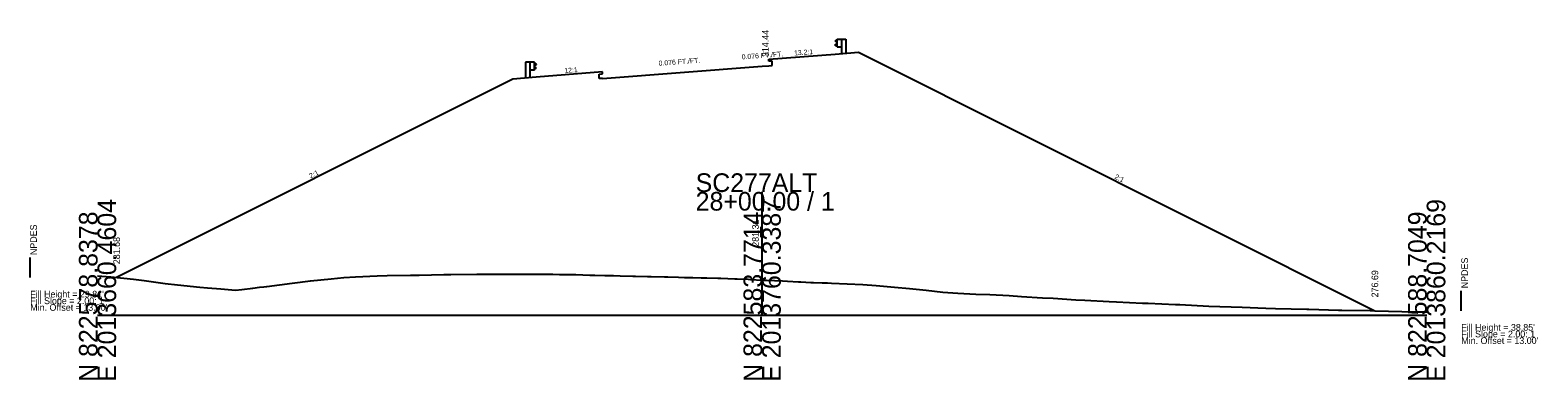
# Model space of a CAD drawing. Extents: x 205929 to 2357175, y -1785700 to 827636.
# Drawn here: x 2017410 to 2017636.9, y 826034.6 to 826087.1 of the extents above; entities that cross this region are included whole.
import ezdxf

# ---------------------------------------------------------------- set-up
doc = ezdxf.new("R2010")
doc.units = 0
for name, color, linetype in [('RD_GPK_XS_Cell', 7, 'Continuous'), ('RD_XS_Base', 7, 'Continuous'), ('RD_XS_EarthShd', 7, 'Continuous'), ('RD_XS_ExGround', 7, 'Continuous'), ('RD_XS_GR', 7, 'Continuous'), ('RD_XS_NPDES', 7, 'Continuous'), ('RD_XS_Pave', 7, 'Continuous'), ('RD_XS_TieSlope', 7, 'Continuous'), ('RD_XS_TX_Elev_EX', 7, 'Continuous'), ('RD_XS_TX_Elev_PR', 7, 'Continuous'), ('RD_XS_TX_ShdSlope', 7, 'Continuous'), ('RD_XS_TX_Slope', 7, 'Continuous'), ('RD_XS_TX_Warning', 7, 'Continuous')]:
    doc.layers.add(name, color=color, linetype=linetype)

msp = doc.modelspace()

# ---------------------------------------------------------------- linework, layer by layer
at = {"layer": 'RD_GPK_XS_Cell'}
for p, q in [((2017520.17, 826044.26), (2017520.17, 826062.8)), ((2017420.17, 826044.26), (2017520.17, 826044.26)), ((2017520.17, 826044.26), (2017620.17, 826044.26))]:
    msp.add_line(p, q, dxfattribs=at)
at = {"layer": 'RD_XS_Base'}
for p, q in [((2017496.17, 826079.88), (2017520.17, 826081.7)), ((2017520.17, 826081.7), (2017521.17, 826081.77))]:
    msp.add_line(p, q, dxfattribs=at)
at = {"layer": 'RD_XS_EarthShd'}
for p, q in [((2017521.17, 826082.77), (2017531.17, 826083.53)), ((2017531.17, 826083.53), (2017534.67, 826083.79)), ((2017496.17, 826080.88), (2017486.17, 826080.04)), ((2017486.17, 826080.04), (2017482.67, 826079.75))]:
    msp.add_line(p, q, dxfattribs=at)
at = {"layer": 'RD_XS_ExGround'}
msp.add_lwpolyline([(2017420.17, 826050.19), (2017420.83, 826050.14), (2017422.19, 826050.02), (2017425.6, 826049.7), (2017427.2, 826049.49), (2017430.37, 826049.05), (2017432.21, 826048.82), (2017435.55, 826048.51), (2017436.71, 826048.41), (2017438.72, 826048.23), (2017440.91, 826048.03), (2017441.89, 826048.14), (2017443.53, 826048.35), (2017444.52, 826048.47), (2017445.17, 826048.54), (2017445.63, 826048.6), (2017449.46, 826049.08), (2017452.23, 826049.46), (2017455.3, 826049.74), (2017457.24, 826049.92), (2017459, 826050.04), (2017462.24, 826050.17), (2017463.77, 826050.22), (2017467.25, 826050.28), (2017468.54, 826050.31), (2017472.26, 826050.39), (2017473.31, 826050.41), (2017477.26, 826050.44), (2017478.08, 826050.43), (2017484.61, 826050.42), (2017485.8, 826050.43), (2017487.47, 826050.43), (2017488.67, 826050.42), (2017489.66, 826050.4), (2017491.07, 826050.39), (2017492.13, 826050.37), (2017494.22, 826050.31), (2017494.98, 826050.3), (2017496.52, 826050.26), (2017497.83, 826050.23), (2017498.82, 826050.2), (2017500.69, 826050.15), (2017501.12, 826050.14), (2017502.92, 826050.1), (2017503.46, 826050.09), (2017505.5, 826050.03), (2017505.97, 826050.02), (2017507.6, 826049.98), (2017508.48, 826049.95), (2017509.73, 826049.93), (2017510.99, 826049.89), (2017511.84, 826049.87), (2017513.49, 826049.83), (2017513.95, 826049.82), (2017516.05, 826049.76), (2017516.4, 826049.75), (2017518.07, 826049.67), (2017518.43, 826049.65), (2017520.17, 826049.56), (2017520.84, 826049.54), (2017522.02, 826049.48), (2017523.26, 826049.42), (2017524.01, 826049.38), (2017525.66, 826049.29), (2017525.99, 826049.28), (2017527.49, 826049.21), (2017527.92, 826049.2), (2017529.19, 826049.15), (2017530.03, 826049.13), (2017530.61, 826049.11), (2017535.32, 826048.9), (2017537.34, 826048.73), (2017540.09, 826048.47), (2017542.34, 826048.29), (2017544.86, 826048.02), (2017547.35, 826047.75), (2017549.64, 826047.61), (2017552.35, 826047.46), (2017554.41, 826047.38), (2017557.36, 826047.25), (2017559.18, 826047.09), (2017562.37, 826046.91), (2017563.95, 826046.82), (2017567.37, 826046.6), (2017568.72, 826046.52), (2017572.38, 826046.33), (2017573.49, 826046.29), (2017577.38, 826046.11), (2017578.26, 826046.08), (2017582.39, 826045.89), (2017583.03, 826045.87), (2017587.4, 826045.65), (2017592.4, 826045.49), (2017595.95, 826045.35), (2017597.41, 826045.29), (2017602.11, 826045.17), (2017602.41, 826045.17), (2017606.88, 826045.05), (2017607.42, 826045.03), (2017611.65, 826044.97), (2017612.43, 826044.94), (2017616.42, 826044.82), (2017617.43, 826044.79), (2017620.17, 826044.77)], dxfattribs=at)
at = {"layer": 'RD_XS_GR'}
for p, q in [((2017531.44, 826085.71), (2017531.17, 826085.51)), ((2017531.17, 826085.51), (2017531.17, 826085.46)), ((2017531.17, 826085.46), (2017531.44, 826085.26)), ((2017531.17, 826084.94), (2017531.44, 826085.14)), ((2017531.17, 826084.89), (2017531.17, 826084.94)), ((2017531.44, 826084.69), (2017531.17, 826084.89)), ((2017531.44, 826084.61), (2017531.44, 826085.78)), ((2017531.44, 826085.78), (2017532.11, 826085.78)), ((2017532.11, 826085.78), (2017532.11, 826083.6)), ((2017532.11, 826085.78), (2017532.78, 826085.78)), ((2017532.78, 826085.78), (2017532.78, 826083.65)), ((2017531.44, 826084.61), (2017532.11, 826084.61)), ((2017484.57, 826082.29), (2017484.57, 826079.91)), ((2017485.24, 826082.29), (2017484.57, 826082.29)), ((2017485.24, 826082.29), (2017485.24, 826079.97)), ((2017485.9, 826082.29), (2017485.24, 826082.29)), ((2017485.9, 826081.13), (2017485.24, 826081.13)), ((2017485.9, 826081.13), (2017485.9, 826082.29)), ((2017485.9, 826082.22), (2017486.17, 826082.02)), ((2017486.17, 826081.97), (2017485.9, 826081.77)), ((2017486.17, 826081.45), (2017485.9, 826081.65)), ((2017485.9, 826081.2), (2017486.17, 826081.4)), ((2017486.17, 826082.02), (2017486.17, 826081.97)), ((2017486.17, 826081.4), (2017486.17, 826081.45))]:
    msp.add_line(p, q, dxfattribs=at)
at = {"layer": 'RD_XS_NPDES'}
for p, q in [((2017410.04, 826049.94), (2017410.04, 826052.94)), ((2017625.37, 826044.95), (2017625.37, 826047.95))]:
    msp.add_line(p, q, dxfattribs=at)
at = {"layer": 'RD_XS_Pave'}
for p, q in [((2017521.17, 826082.44), (2017521.17, 826082.77)), ((2017521.67, 826082.48), (2017521.17, 826082.44)), ((2017521.67, 826081.81), (2017521.67, 826082.48)), ((2017495.67, 826080.51), (2017496.17, 826080.55)), ((2017495.67, 826079.84), (2017495.67, 826080.51)), ((2017496.17, 826080.55), (2017496.17, 826080.88)), ((2017521.17, 826081.77), (2017521.67, 826081.81)), ((2017496.17, 826079.88), (2017495.67, 826079.84))]:
    msp.add_line(p, q, dxfattribs=at)
at = {"layer": 'RD_XS_TieSlope'}
for p, q in [((2017534.67, 826083.79), (2017612.37, 826044.95)), ((2017482.67, 826079.75), (2017423.04, 826049.94))]:
    msp.add_line(p, q, dxfattribs=at)

# ---------------------------------------------------------------- texts
at = {"layer": 'RD_GPK_XS_Cell'}
for s, p in [('SC277ALT', (2017510.17, 826062.8)), ('28+00.00 / 1', (2017510.17, 826060))]:
    msp.add_text(s, height=2.8, dxfattribs=at).set_placement(p)
for s, p in [('E 2013660.4604', (2017422.97, 826034.26)), ('N 822583.7714', (2017520.17, 826034.26)), ('E 2013760.3387', (2017522.97, 826034.26)), ('E 2013860.2169', (2017622.97, 826034.26)), ('N 822578.8378', (2017420.17, 826034.26)), ('N 822588.7049', (2017620.17, 826034.26))]:
    msp.add_text(s, height=2.8, rotation=90, dxfattribs=at).set_placement(p)
at = {"layer": 'RD_XS_TX_Elev_EX'}
msp.add_text('281.31', height=1, rotation=90, dxfattribs=at).set_placement((2017519.67, 826054.56))
at = {"layer": 'RD_XS_TX_Elev_PR'}
for s, p in [(' 314.44', (2017521.17, 826082.7)), ('281.68', (2017423.54, 826051.94)), ('276.69', (2017612.87, 826046.95))]:
    msp.add_text(s, height=1, rotation=90, dxfattribs=at).set_placement(p)
at = {"layer": 'RD_XS_TX_ShdSlope'}
for s, rotation, p in [('13.2:1', 4.3347, (2017525, 826083.31)), ('12:1', 4.7636, (2017490.44, 826080.65))]:
    msp.add_text(s, height=0.75, rotation=rotation, dxfattribs=at).set_placement(p)
at = {"layer": 'RD_XS_TX_Slope'}
for s, rotation, p in [('0.076 FT./FT.', 4.3347, (2017504.62, 826081.77)), ('0.076 FT./FT.', 4.3347, (2017517.12, 826082.72)), ('2:1', 26.5651, (2017452.24, 826064.82)), ('2:1', 333.4349, (2017573.13, 826064.85))]:
    msp.add_text(s, height=0.75, rotation=rotation, dxfattribs=at).set_placement(p)
at = {"layer": 'RD_XS_TX_Warning'}
for p in [(2017411.04, 826052.94), (2017626.37, 826047.95)]:
    msp.add_text(' NPDES', height=1, rotation=90, dxfattribs=at).set_placement(p)
for s, p in [("Fill Height = 29.81' ", (2017410.04, 826046.94)), ('Fill Slope = 2.00: 1', (2017410.04, 826045.94)), ("Min. Offset = 13.00' ", (2017410.04, 826044.94)), ("Fill Height = 38.85' ", (2017625.37, 826041.95)), ('Fill Slope = 2.00: 1', (2017625.37, 826040.95)), ("Min. Offset = 13.00' ", (2017625.37, 826039.95))]:
    msp.add_text(s, height=1, dxfattribs=at).set_placement(p)

doc.saveas('drawing.dxf')
